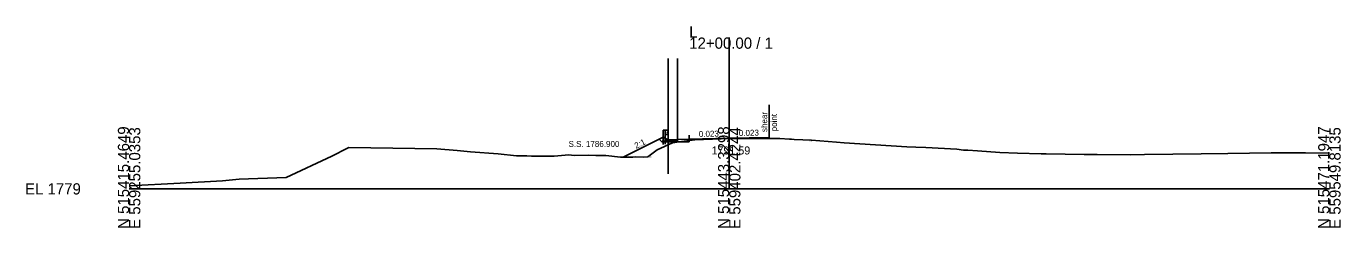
# Model space of a CAD drawing. Extents: x -26 to 1303, y -10 to 9545.
# Drawn here: x -25.7 to 302.8, y 4490.3 to 4540.6 of the extents above; entities that cross this region are included whole.
import ezdxf

# ---------------------------------------------------------------- set-up
doc = ezdxf.new("R2010")
doc.units = 0
for name, color, linetype in [('Exist Cross Section Cell', 7, 'Continuous'), ('Exist XS Center Line Elevation Label', 7, 'Continuous'), ('Exist XS Ground Line', 7, 'Continuous'), ('Prop XS Dump Level', 7, 'Continuous'), ('Prop XS EOT Tick Mark', 7, 'Continuous'), ('Prop XS Finish Grade', 7, 'Continuous'), ('Prop XS Finish Grade Earthwork', 7, 'Continuous'), ('Prop XS Finish Grade Paved Shoulder', 7, 'Continuous'), ('Prop XS Finish Grade Pavement', 7, 'Continuous'), ('Prop XS Guardrail', 7, 'Continuous'), ('Prop XS Pvmt Edge Slope', 7, 'Continuous'), ('Prop XS SE Text', 7, 'Continuous'), ('Prop XS Shear Point Label', 7, 'Continuous'), ('Prop XS Side Slope Text', 7, 'Continuous'), ('Prop XS SS Elevation Text', 7, 'Continuous'), ('Prop XS Subgrade Earthwork', 7, 'Continuous'), ('Scratch_Level_3', 7, 'Continuous'), ('Typical Curb CELL', 7, 'Continuous')]:
    doc.layers.add(name, color=color, linetype=linetype)

msp = doc.modelspace()

# ---------------------------------------------------------------- linework, layer by layer
at = {"layer": 'Exist Cross Section Cell'}
for p, q in [((150, 4500), (150, 4537.8)), ((0, 4500), (150, 4500)), ((150, 4500), (300, 4500))]:
    msp.add_line(p, q, dxfattribs=at)
at = {"layer": 'Exist XS Ground Line'}
for p, q in [((131.99, 4509.79), (135.82, 4511.51)), ((135.82, 4511.51), (138.09, 4511.85)), ((138.09, 4511.85), (141.4, 4512.27)), ((141.4, 4512.27), (150.22, 4512.6)), ((150.22, 4512.6), (162.62, 4512.58)), ((162.62, 4512.58), (165.06, 4512.44)), ((165.06, 4512.44), (165.57, 4512.39)), ((165.57, 4512.39), (166.22, 4512.32)), ((166.22, 4512.32), (170.58, 4512.16)), ((170.58, 4512.16), (176.85, 4511.67)), ((176.85, 4511.67), (178.73, 4511.5)), ((178.73, 4511.5), (194.37, 4510.54)), ((39.27, 4502.82), (50.67, 4508.19)), ((50.67, 4508.19), (51.64, 4508.68)), ((51.64, 4508.68), (53.56, 4509.64)), ((53.56, 4509.64), (54.92, 4510.36)), ((54.92, 4510.36), (76.92, 4509.97)), ((76.92, 4509.97), (81.99, 4509.57)), ((81.99, 4509.57), (85.32, 4509.28)), ((85.32, 4509.28), (92.25, 4508.75)), ((92.25, 4508.75), (96.82, 4508.23)), ((96.82, 4508.23), (99.43, 4508.27)), ((99.43, 4508.27), (100.58, 4508.14)), ((100.58, 4508.14), (104.45, 4508.18)), ((104.45, 4508.18), (105.38, 4508.15)), ((105.38, 4508.15), (106.26, 4508.13)), ((106.26, 4508.13), (109.88, 4508.49)), ((109.88, 4508.49), (111.28, 4508.37)), ((111.28, 4508.37), (114.74, 4508.39)), ((114.74, 4508.39), (116.67, 4508.33)), ((116.67, 4508.33), (119.2, 4508.3)), ((119.2, 4508.3), (122.84, 4507.9)), ((122.84, 4507.9), (125.88, 4507.92)), ((125.88, 4507.92), (126.55, 4507.97)), ((126.55, 4507.97), (128.66, 4507.91)), ((128.66, 4507.91), (129.64, 4508.01)), ((129.64, 4508.01), (130.03, 4508.22)), ((130.03, 4508.22), (131.99, 4509.79)), ((194.37, 4510.54), (196.63, 4510.41)), ((196.63, 4510.41), (199.15, 4510.36)), ((199.15, 4510.36), (206.91, 4509.94)), ((206.91, 4509.94), (208.58, 4509.69)), ((208.58, 4509.69), (209.68, 4509.67)), ((209.68, 4509.67), (212.02, 4509.54)), ((212.02, 4509.54), (217.67, 4509.05)), ((217.67, 4509.05), (222.06, 4508.92)), ((222.06, 4508.92), (227.93, 4508.77)), ((227.93, 4508.77), (229.25, 4508.71)), ((229.25, 4508.71), (238.7, 4508.56)), ((238.7, 4508.56), (241.97, 4508.55)), ((241.97, 4508.55), (250.18, 4508.53)), ((250.18, 4508.53), (253.81, 4508.58)), ((253.81, 4508.58), (267.95, 4508.73)), ((267.95, 4508.73), (274.61, 4508.85)), ((274.61, 4508.85), (285.48, 4508.96)), ((285.48, 4508.96), (294.06, 4508.98)), ((294.06, 4508.98), (300, 4508.92)), ((0, 4500.8), (12.74, 4501.42)), ((12.74, 4501.42), (23.34, 4501.98)), ((23.34, 4501.98), (27.52, 4502.45)), ((27.52, 4502.45), (39.27, 4502.82))]:
    msp.add_line(p, q, dxfattribs=at)
at = {"layer": 'Prop XS Dump Level'}
for p, q in [((150, 4512.63), (140, 4512.4)), ((160, 4512.86), (150, 4512.63))]:
    msp.add_line(p, q, dxfattribs=at)
at = {"layer": 'Prop XS EOT Tick Mark'}
for p, q in [((140, 4512.4), (140, 4513.4)), ((160, 4512.86), (160, 4513.86))]:
    msp.add_line(p, q, dxfattribs=at)
at = {"layer": 'Prop XS Finish Grade'}
for p, q in [((133.45, 4512.88), (132.49, 4512.4)), ((133.45, 4512.88), (134.08, 4512.59)), ((134.08, 4512.59), (134.09, 4511.72))]:
    msp.add_line(p, q, dxfattribs=at)
at = {"layer": 'Prop XS Finish Grade Earthwork'}
msp.add_line((132.49, 4512.4), (123.49, 4507.9), dxfattribs=at)
at = {"layer": 'Prop XS Finish Grade Paved Shoulder'}
msp.add_line((140, 4512.4), (137.1, 4512.33), dxfattribs=at)
at = {"layer": 'Prop XS Finish Grade Pavement'}
for p, q in [((140, 4512.4), (150, 4512.63)), ((150, 4512.63), (160, 4512.86))]:
    msp.add_line(p, q, dxfattribs=at)
at = {"layer": 'Prop XS Guardrail'}
for p, q in [((133.45, 4514.69), (133.95, 4514.69)), ((133.45, 4512.17), (133.45, 4514.69)), ((133.95, 4514.69), (134.45, 4514.69)), ((133.95, 4514.69), (133.95, 4512.21)), ((134.45, 4514.69), (134.74, 4514.49)), ((134.74, 4514.37), (134.45, 4514.17)), ((134.45, 4514.17), (134.45, 4514.08)), ((134.45, 4514.08), (134.74, 4513.88)), ((134.74, 4514.49), (134.77, 4514.43)), ((134.77, 4514.43), (134.74, 4514.37)), ((133.45, 4512.17), (133.45, 4511.12)), ((134.45, 4513.56), (133.95, 4513.56)), ((133.95, 4512.21), (133.95, 4511.16)), ((134.74, 4513.76), (134.45, 4513.56)), ((134.74, 4513.88), (134.77, 4513.82)), ((134.77, 4513.82), (134.74, 4513.76))]:
    msp.add_line(p, q, dxfattribs=at)
at = {"layer": 'Prop XS Pvmt Edge Slope'}
for p, q in [((133.27, 4511.91), (133.18, 4511.71)), ((134.08, 4511.91), (133.27, 4511.91))]:
    msp.add_line(p, q, dxfattribs=at)
at = {"layer": 'Prop XS Shear Point Label'}
msp.add_line((160, 4512.86), (160, 4520.96), dxfattribs=at)
at = {"layer": 'Prop XS Subgrade Earthwork'}
for p, q in [((133.18, 4511.71), (132.49, 4512.4)), ((140, 4511.77), (133.18, 4511.71)), ((140, 4511.77), (140, 4512.09))]:
    msp.add_line(p, q, dxfattribs=at)
at = {"layer": 'Scratch_Level_3'}
for p, q in [((134.77, 4532.56), (134.77, 4503.78)), ((137.1, 4532.56), (137.1, 4512.33))]:
    msp.add_line(p, q, dxfattribs=at)
at = {"layer": 'Typical Curb CELL'}
for p, q in [((134.08, 4511.91), (134.08, 4512.59)), ((134.77, 4512.25), (134.08, 4512.59)), ((134.08, 4511.91), (137.1, 4511.91)), ((134.12, 4512.21), (134.27, 4512.26)), ((134.25, 4512.17), (134.12, 4512.21)), ((134.27, 4512.26), (134.25, 4512.17)), ((134.78, 4512.13), (134.68, 4512.05)), ((134.68, 4512.05), (134.85, 4512.01)), ((137.09, 4512.33), (134.77, 4512.25)), ((134.85, 4512.01), (134.78, 4512.13)), ((135.53, 4512.18), (135.49, 4512.07)), ((135.49, 4512.07), (135.61, 4512.06)), ((135.61, 4512.06), (135.53, 4512.18)), ((136.03, 4512.13), (135.93, 4512.05)), ((135.93, 4512.05), (136.1, 4512.01)), ((136.1, 4512.01), (136.03, 4512.13)), ((136.78, 4512.18), (136.74, 4512.07)), ((136.74, 4512.07), (136.86, 4512.06)), ((136.86, 4512.06), (136.78, 4512.18)), ((137.1, 4512.33), (137.1, 4512.33)), ((137.1, 4511.91), (137.1, 4512.32))]:
    msp.add_line(p, q, dxfattribs=at)
for centre in [(134.14, 4512.3), (134.24, 4512.02), (134.36, 4512.07), (134.62, 4512.1), (134.63, 4512.05), (134.81, 4511.97), (134.84, 4512.07), (135.03, 4512.03), (135.08, 4512.14), (135.21, 4512.12), (135.24, 4511.99), (135.3, 4512.02), (135.49, 4512.02), (135.61, 4512.07), (135.7, 4512.06), (135.8, 4512.02), (135.86, 4512.16), (135.87, 4512.1), (135.88, 4512.05), (136.09, 4512.07), (136.28, 4512.03), (136.33, 4512.14), (136.38, 4512.11), (136.46, 4512.12), (136.49, 4511.99), (136.54, 4512.02), (136.6, 4512.2), (136.97, 4512.28), (137.01, 4512.15)]:
    msp.add_circle(centre, 0.00802, dxfattribs=at)
msp.add_arc((137.09, 4512.32), 0.0104, 0, 92.048, dxfattribs=at)

# ---------------------------------------------------------------- texts
at = {"layer": 'Exist Cross Section Cell'}
for s, p in [('L', (140, 4537.8)), ('12+00.00 / 1', (140, 4535)), ('EL 1779', (-26, 4498.6))]:
    msp.add_text(s, height=2.8, dxfattribs=at).set_placement(p)
for s, p in [('N 515415.4649', (0, 4490)), ('E 559255.0353', (2.8, 4490)), ('N 515443.3298', (150, 4490)), ('E 559402.4244', (152.8, 4490)), ('N 515471.1947', (300, 4490)), ('E 559549.8135', (302.8, 4490))]:
    msp.add_text(s, height=2.8, rotation=90, dxfattribs=at).set_placement(p)
at = {"layer": 'Exist XS Center Line Elevation Label'}
msp.add_text('1791.59', height=2, dxfattribs=at).set_placement((145.59, 4508.59))
at = {"layer": 'Prop XS Dump Level'}
for s, height, p in [('Case1', 0.04, (163, 4512.71)), ('Eop', 0.3, (170, 4511.88)), ('Eop', 0.3, (130, 4507.9))]:
    msp.add_text(s, height=height, dxfattribs=at).set_placement(p)
at = {"layer": 'Prop XS SE Text'}
for p in [(142.41, 4512.95), (152.41, 4513.18)]:
    msp.add_text('0.023', height=1.5, rotation=1.3214, dxfattribs=at).set_placement(p)
at = {"layer": 'Prop XS Shear Point Label'}
for s, p in [('shear', (159.49, 4514.19)), (' point', (161.93, 4513.81))]:
    msp.add_text(s, height=1.5, rotation=90, dxfattribs=at).set_placement(p)
at = {"layer": 'Prop XS Side Slope Text'}
msp.add_text('2:1', height=1.5, rotation=26.5651, dxfattribs=at).set_placement((126.76, 4509.98))
at = {"layer": 'Prop XS SS Elevation Text'}
msp.add_text('S.S. 1786.900', height=1.5, dxfattribs=at).set_placement((109.84, 4510.47))

doc.saveas('drawing.dxf')
